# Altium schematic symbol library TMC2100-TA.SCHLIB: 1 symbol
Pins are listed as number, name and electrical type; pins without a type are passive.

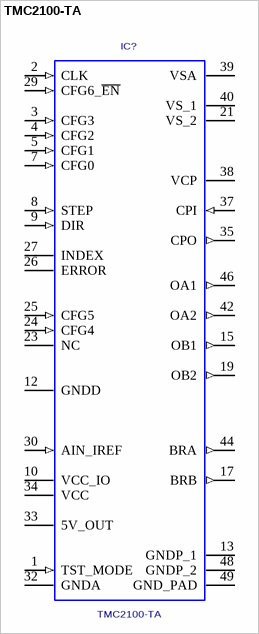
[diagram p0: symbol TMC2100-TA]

## TMC2100-TA
designator IC?
Standalone Step/Dir driver for two-phase bipolar stepper motor, TQFP48-EP(7x7); Manufacturer: TRINAMIC; Geometry.Height: 1.2mm; PCB DECAL: TMC_TQFP48-EP_0.5_7.0X7.0
footprint TMC_TQFP48-EP_0.5_7.0X7.0
pins: 1 TST_MODE (in), 2 CLK (in), 3 CFG3 (in), 4 CFG2 (in), 5 CFG1 (in), 7 CFG0 (in), 8 STEP (in), 9 DIR (in), 10 VCC_IO (power), 12 GNDD (power), 13 GNDP_1 (power), 15 OB1 (out), 17 BRB (out), 19 OB2 (out), 21 VS_2 (power), 23 NC, 24 CFG4 (in), 25 CFG5 (in), 26 ERROR (oc), 27 INDEX (oc), 29 CFG6_~{EN} (in), 30 AIN_IREF (in), 32 GNDA (power), 33 5V_OUT (power), 34 VCC (power), 35 CPO (out), 37 CPI (in), 38 VCP (power), 39 VSA (power), 40 VS_1 (power), 42 OA2 (out), 44 BRA (out), 46 OA1 (out), 48 GNDP_2 (power), 49 GND_PAD (power)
